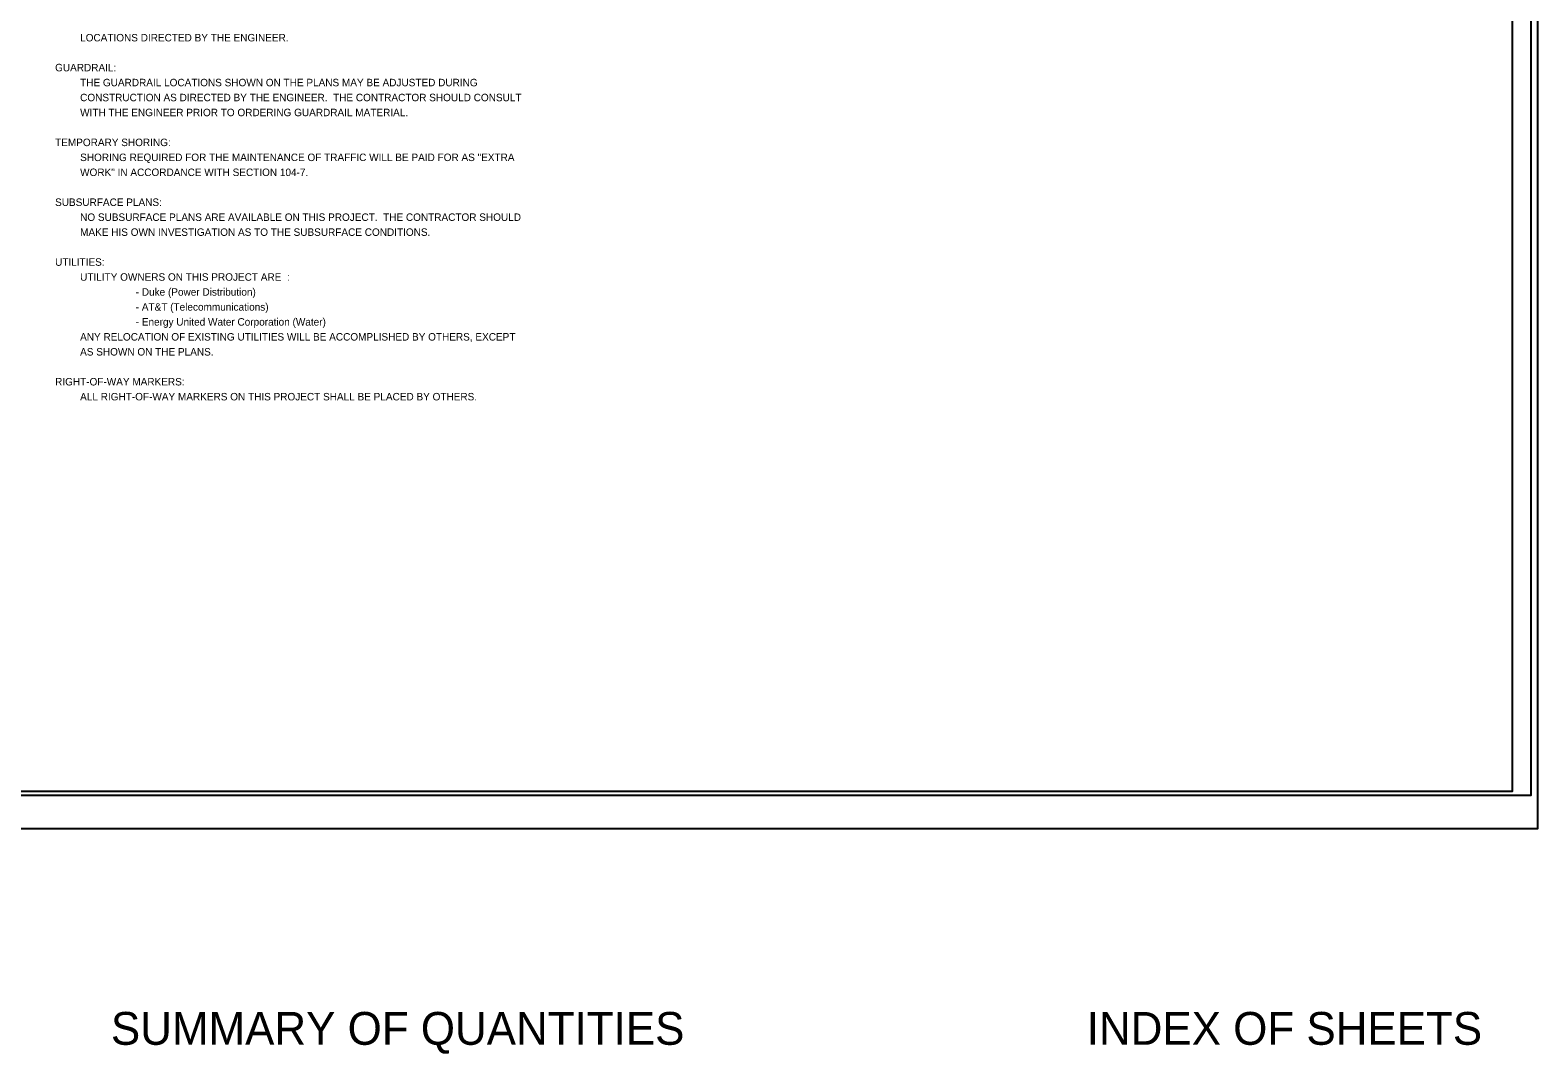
# Model space of a CAD drawing. Extents: x 1728265 to 1732106, y 539919 to 543766.
# Drawn here: x 1730130 to 1731137, y 542400 to 543084 of the extents above; entities that cross this region are included whole.
import ezdxf

# ---------------------------------------------------------------- set-up
doc = ezdxf.new("R2010")
doc.units = 0
for name, color, linetype in [('Default', 7, 'Continuous'), ('Sheet Cutting Line CELL', 7, 'Continuous'), ('Sheet Plot Border Inside CELL', 7, 'Continuous'), ('Sheet Plot Border Outside CELL', 7, 'Continuous'), ('Sheet Summary CELL', 7, 'Continuous')]:
    doc.layers.add(name, color=color, linetype=linetype)

msp = doc.modelspace()

# ---------------------------------------------------------------- linework, layer by layer
at = {"layer": 'Sheet Cutting Line CELL'}
msp.add_line((1729453.3, 542550.6), (1731137.3, 542550.6), dxfattribs=at)
at = {"layer": 'Sheet Plot Border Inside CELL'}
msp.add_lwpolyline([(1731132.8, 543628.2), (1729466.3, 543628.2), (1729466.3, 542573.1), (1731132.8, 542573.1)], close=True, dxfattribs=at)
at = {"layer": 'Sheet Plot Border Outside CELL'}
msp.add_lwpolyline([(1731137.3, 543650.6), (1729453.3, 543650.6), (1729453.3, 542550.6), (1731137.3, 542550.6)], close=True, dxfattribs=at)
at = {"layer": 'Sheet Summary CELL'}
msp.add_lwpolyline([(1731120.3, 543625.6), (1729620.3, 543625.6), (1729620.3, 542575.6), (1731120.3, 542575.6)], close=True, dxfattribs=at)

# ---------------------------------------------------------------- texts
at = {"layer": 'Default'}
for s, p in [('         LOCATIONS DIRECTED BY THE ENGINEER.  ', (1730146.5, 543076.9)), ('GUARDRAIL:  ', (1730146.5, 543056.9)), ('         THE GUARDRAIL LOCATIONS SHOWN ON THE PLANS MAY BE ADJUSTED DURING ', (1730146.5, 543046.9)), ('         CONSTRUCTION AS DIRECTED BY THE ENGINEER.  THE CONTRACTOR SHOULD CONSULT', (1730146.5, 543036.9)), ('         WITH THE ENGINEER PRIOR TO ORDERING GUARDRAIL MATERIAL.', (1730146.5, 543026.9)), ('TEMPORARY SHORING:  ', (1730146.5, 543006.9)), ('         SHORING REQUIRED FOR THE MAINTENANCE OF TRAFFIC WILL BE PAID FOR AS "EXTRA ', (1730146.5, 542996.9)), ('         WORK" IN ACCORDANCE WITH SECTION 104-7.  ', (1730146.5, 542986.9)), ('SUBSURFACE PLANS:  ', (1730146.5, 542966.9)), ('         NO SUBSURFACE PLANS ARE AVAILABLE ON THIS PROJECT.  THE CONTRACTOR SHOULD ', (1730146.5, 542956.9)), ('         MAKE HIS OWN INVESTIGATION AS TO THE SUBSURFACE CONDITIONS.  ', (1730146.5, 542946.9)), ('UTILITIES:  ', (1730146.5, 542926.9)), ('         UTILITY OWNERS ON THIS PROJECT ARE  :', (1730146.5, 542916.9)), ('                             - Duke (Power Distribution)', (1730146.5, 542906.9)), ('                             - AT&T (Telecommunications)', (1730146.5, 542896.9)), ('                             - Energy United Water Corporation (Water)', (1730146.5, 542886.9)), ('         ANY RELOCATION OF EXISTING UTILITIES WILL BE ACCOMPLISHED BY OTHERS, EXCEPT ', (1730146.5, 542876.9)), ('         AS SHOWN ON THE PLANS.  ', (1730146.5, 542866.9)), ('RIGHT-OF-WAY MARKERS:  ', (1730146.5, 542846.9)), ('         ALL RIGHT-OF-WAY MARKERS ON THIS PROJECT SHALL BE PLACED BY OTHERS.  ', (1730146.5, 542836.9))]:
    msp.add_text(s, height=5, dxfattribs=at).set_placement(p)
at = {"layer": 'Sheet Summary CELL'}
for s, p in [('SUMMARY OF QUANTITIES', (1730183.8, 542406.1)), ('INDEX OF SHEETS', (1730835.9, 542406.1))]:
    msp.add_text(s, height=21.95, dxfattribs=at).set_placement(p)

doc.saveas('drawing.dxf')
